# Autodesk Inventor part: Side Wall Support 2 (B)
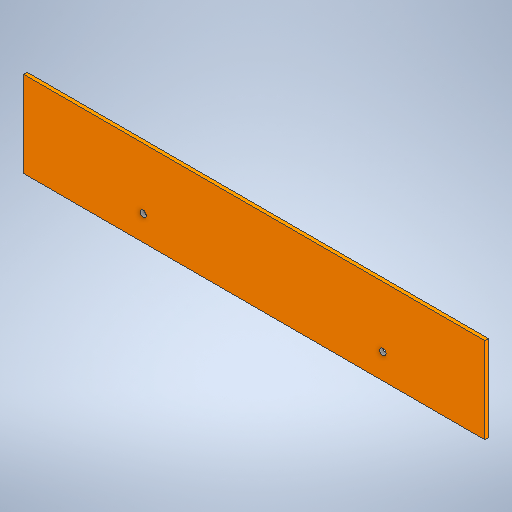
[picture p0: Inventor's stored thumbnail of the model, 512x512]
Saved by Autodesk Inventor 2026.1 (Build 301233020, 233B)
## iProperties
Created: 2026-11
Part Number: Side Wall Support 2 (B)
Material: Generic
Document SubType Name: Modeling
Designer: hp
Density: 1 g/cm^3
Appearance: Default
Author: hp
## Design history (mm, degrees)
sketch "Sketch1"
  geometry: L1 (0, 0)-(645, 0); L2 (645, 0)-(645, 120); L3 (645, 120)-(0, 120); L4 (0, 120)-(0, 0)
  constraints: 8 end point, 2 parallel, 1 horizontal, 1 perpendicular
  dimensions: "d0" = 645 distance of L3.end L2.end; "d1" = 120 distance of L2.end L1.end
extrude "Extrusion1" new body sketch "Sketch1" distance "d2" = 5; taper "d3" = 0 deg
sketch "Sketch3"
  geometry: 2 further points
hole "Hole2" sketch "Sketch3" at (502.5, 35), (167.5, 35) diameter "d11" = 9; stored, may be unused: countersink angle "d15" = 90 deg, drill point angle "d17" = 0 deg; dims "d12" = 6, "d13" = 4, "d14" = 2, "d16" = 8
body "Solid1"
